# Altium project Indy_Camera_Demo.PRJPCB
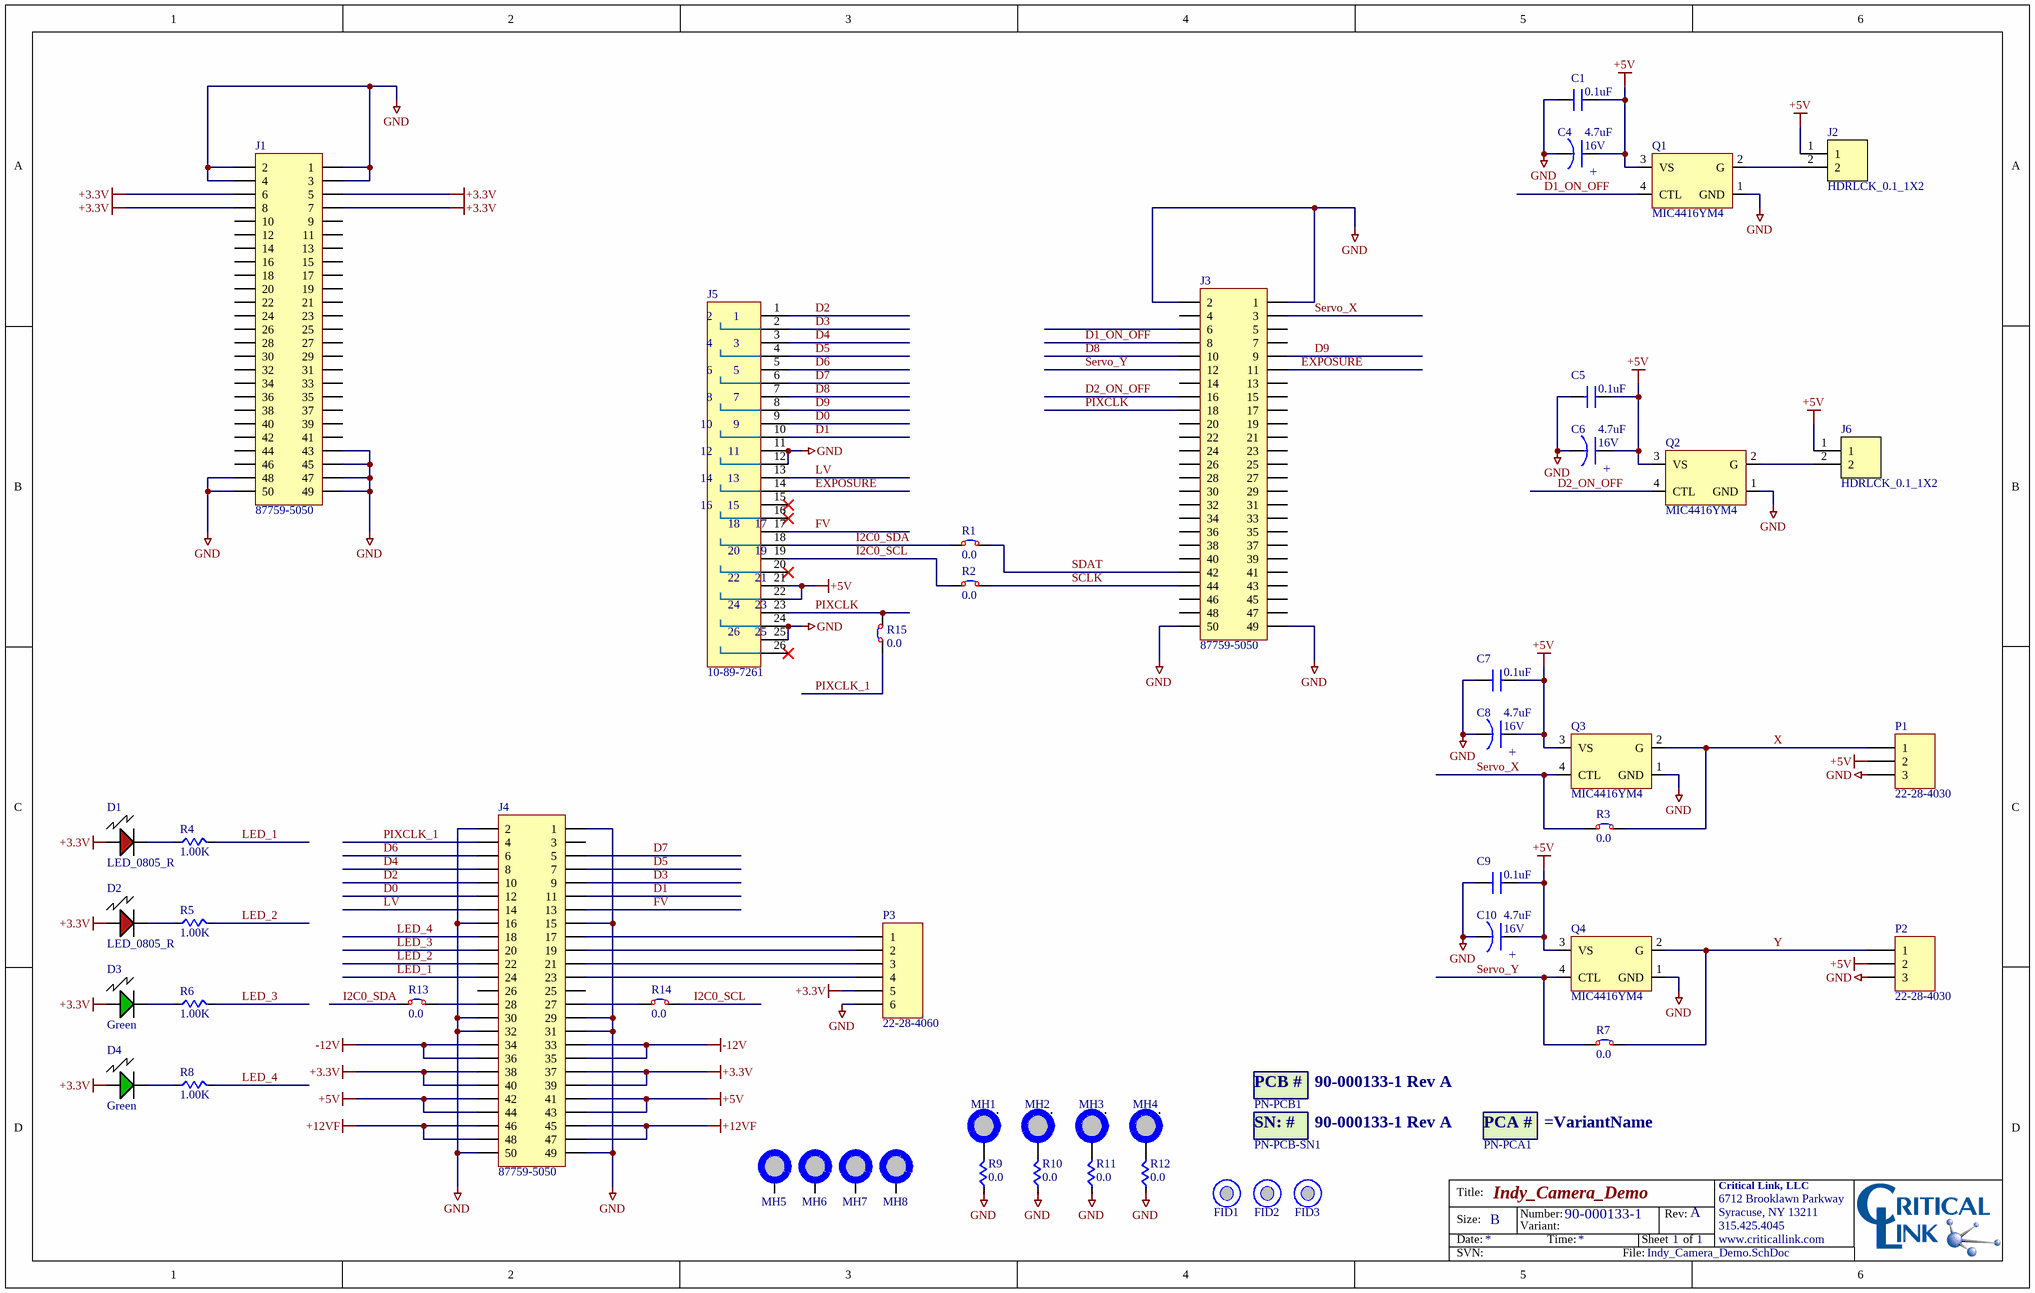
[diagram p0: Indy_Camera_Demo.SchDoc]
1 sheet, 54 parts. Net scope: global (net labels, ports and power ports of the same name join across sheets).
Board file: Indy_Camera_Demo.PcbDoc

## Sheet Indy_Camera_Demo.SchDoc: Indy_Camera_Demo
size B; Organization: Critical Link, LLC; Address1: 6712 Brooklawn Parkway; Address2: Syracuse, NY 13211; Address3: 315.425.4045; Address4: www.criticallink.com; DocumentNumber: 90-000133-1; Revision: A; SheetNumber: 1; SheetTotal: 1; CompanyName: Critical Link, LLC; PageSetup: Record=PageOptions|CenterHorizontal=True|CenterVertical=True|PrintScale=0.70|XCorrection=1.00|YCorrection=1.00|PrintKind=0|BorderSize=5000000|LeftOffset=0|BottomOffset=0|Orientation=2|PaperLength=1000|PaperWidth=1000|Scale=100|PaperSource=7|PrintQuality=-4|MediaType=1|DitherType=10|PaperKind=Letter|PrintScaleMode=1

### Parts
C1  0.1uF  [0603]
C4  4.7uF  Voltage: 16V  [SMD_TAN_A]
C5  0.1uF  [0603]
C6  4.7uF  Voltage: 16V  [SMD_TAN_A]
C7  0.1uF  [0603]
C8  4.7uF  Voltage: 16V  [SMD_TAN_A]
C9  0.1uF  [0603]
C10  4.7uF  Voltage: 16V  [SMD_TAN_A]
D1  LED_0805_R  [LED805]
D2  LED_0805_R  [LED805]
D3  Green  [LED805]
D4  Green  [LED805]
FID1  FIDUCIAL  [FIDUCIAL]  (value not drawn)  (no BOM)
FID2  FIDUCIAL  [FIDUCIAL]  (value not drawn)  (no BOM)
FID3  FIDUCIAL  [FIDUCIAL]  (value not drawn)  (no BOM)
J1  87759-5050  [87759-5050]
J2  HDRLCK_0.1_1X2  [22-23-2021]
J3  87759-5050  [87759-5050]
J4  87759-5050  [87759-5050]
J5  10-89-7261  [HDR_M_100_2x13x240_THR_V_G]
J6  HDRLCK_0.1_1X2  [22-23-2021]
MH1  MH_5-32x  [MH_5-32x]  (value not drawn)  (no BOM)
MH2  MH_5-32x  [MH_5-32x]  (value not drawn)  (no BOM)
MH3  MH_5-32x  [MH_5-32x]  (value not drawn)  (no BOM)
MH4  MH_5-32x  [MH_5-32x]  (value not drawn)  (no BOM)
MH5  MH  [MH125]  (value not drawn)  (no BOM)
MH6  MH  [MH125]  (value not drawn)  (no BOM)
MH7  MH  [MH125]  (value not drawn)  (no BOM)
MH8  MH  [MH125]  (value not drawn)  (no BOM)
P1  22-28-4030  [HDR_M_100_1x3x230_THR]
P2  22-28-4030  [HDR_M_100_1x3x230_THR]
P3  22-28-4060  [HDR1X6]
PN-PCA1  PN-PCA  [PN-PCA]  (value not drawn)  (no BOM)
PN-PCB1  90-000133-1 Rev A  [PN-PCB]  (mechanical)
PN-PCB-SN1  90-000133-1 Rev A  [PN-PCB]  (no BOM)
Q1  MIC4416YM4  [SM/SOT143_1234]
Q2  MIC4416YM4  [SM/SOT143_1234]
Q3  MIC4416YM4  [SM/SOT143_1234]
Q4  MIC4416YM4  [SM/SOT143_1234]
R1  0.0  [0603]
R2  0.0  [0603]
R3  0.0  [0805]
R4  1.00K  [0603]
R5  1.00K  [0603]
R6  1.00K  [0603]
R7  0.0  [0805]
R8  1.00K  [0603]
R9  0.0  [1206]
R10  0.0  [1206]
R11  0.0  [1206]
R12  0.0  [1206]
R13  0.0  [0603]
R14  0.0  [0603]
R15  0.0  [0603]

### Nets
+3.3V: D1.1(A) D2.1(A) D3.1(A) D4.1(A) J1.5 J1.6 J1.7 J1.8 J4.37 J4.38 J4.39 J4.40 P3.5
+5V: C1.1 C4.1 C5.1 C6.1 C7.1 C8.1 C9.1 C10.1 J2.1 J4.41 J4.42 J4.43 J4.44 J5.21(P21) J5.22(P22) J6.1 P1.2 P2.2 Q1.3(VS) Q2.3(VS) Q3.3(VS) Q4.3(VS)
+12VF: J4.45 J4.46 J4.47 J4.48
-12V: J4.33 J4.34 J4.35 J4.36
GND: C1.2 C4.2 C5.2 C6.2 C7.2 C8.2 C9.2 C10.2 J1.1 J1.2 J1.3 J1.4 J1.43 J1.45 J1.47 J1.48 J1.49 J1.50 J3.1 J3.2 J3.49 J3.50 J4.1 J4.2 J4.15 J4.16 J4.29 J4.30 J4.31 J4.32 J4.49 J4.50 J5.11(P11) J5.12(P12) J5.24(P24) J5.25(P25) P1.3 P2.3 P3.6 Q1.1(GND) Q2.1(GND) Q3.1(GND) Q4.1(GND) R9.2 R10.2 R11.2 R12.2
D0: J4.12 J5.9(P9)
D1: J4.11 J5.10(P10)
D1_ON_OFF: J3.8 Q1.4(CTL)
D2: J4.10 J5.1(P1)
D2_ON_OFF: J3.16 Q2.4(CTL)
D3: J4.9 J5.2(P2)
D4: J4.8 J5.3(P3)
D5: J4.7 J5.4(P4)
D6: J4.6 J5.5(P5)
D7: J4.5 J5.6(P6)
D8: J3.10 J5.7(P7)
D9: J3.9 J5.8(P8)
EXPOSURE: J3.11 J5.14(P14)
FV: J4.13 J5.17(P17)
I2C0_SCL: J5.19(P19) R2.1(TOP) R14.2(BOT)
I2C0_SDA: J5.18(P18) R1.1(TOP) R13.1(TOP)
LED_1: J4.24 R4.1
LED_2: J4.22 R5.1
LED_3: J4.20 R6.1
LED_4: J4.18 R8.1
LV: J4.14 J5.13(P13)
PIXCLK: J3.18 J5.23(P23) R15.2(BOT)
PIXCLK_1: J4.4 R15.1(TOP)
SCLK: J3.44 R2.2(BOT)
SDAT: J3.42 R1.2(BOT)
Servo_X: J3.3 Q3.4(CTL) R3.1(TOP)
Servo_Y: J3.12 Q4.4(CTL) R7.1(TOP)
X: P1.1 Q3.2(G) R3.2(BOT)
Y: P2.1 Q4.2(G) R7.2(BOT)
NetD1_2: D1.2(C) R4.2
NetD2_2: D2.2(C) R5.2
NetD3_2: D3.2(C) R6.2
NetD4_2: D4.2(C) R8.2
NetJ2_2: J2.2 Q1.2(G)
NetJ4_17: J4.17 P3.1
NetJ4_19: J4.19 P3.2
NetJ4_21: J4.21 P3.3
NetJ4_23: J4.23 P3.4
NetJ4_27: J4.27 R14.1(TOP)
NetJ4_28: J4.28 R13.2(BOT)
NetJ6_2: J6.2 Q2.2(G)
NetMH1_0: MH1.0 R9.1
NetMH2_0: MH2.0 R10.1
NetMH3_0: MH3.0 R11.1
NetMH4_0: MH4.0 R12.1

Not connected (* = marked no-connect by the designer): J1 9 10 11 12 13 14 15 16 17 18 19 20 21 22 23 24 25 26 27 28 29 30 31 32 33 34 35 36 37 38 39 40 41 42 44 46; J3 4 5 6 7 13 14 15 17 19 20 21 22 23 24 25 26 27 28 29 30 31 32 33 34 35 36 37 38 39 40 41 43 45 46 47 48; J4 3 25 26; J5 15(P15)* 16(P16)* 20(P20)* 26(P26)*; MH1 1; MH2 1; MH3 1; MH4 1; MH5 0; MH6 0; MH7 0; MH8 0

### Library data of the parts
C1 C5 C7 C9 = CAP_X7R_0603_50V: CAP CER .10UF 50V X7R 10% 0603; Part_Type: Ceramic; Type: capacitor; User: Adam; Mfg_PN: 06035C104KAT2A; Dist1: Digi-Key; Dist1_PN: 478-5052-1-ND; Mfg: AVX Corporation; PbFree_Status: Lead free; $/100: 0.048800; $/500: 0.028120; $/1000: 0.019500; ID: 66; Mfg_PID: 5406; QtyAvail: 443230; dist_PID: 1629; dist_pref: 100; $/10: 0.083000; $/ea: 0.000000
C4 C6 C8 C10 = T491A475K016AT: CAPACITOR TANT 4.7UF 16V 10% SMD; Mfg: Kemet; Dist1_PN: 399-3697-1-ND; Dist1: Digi-Key; User: Huy; PbFree_Status: Lead Free; $/100: 0.152000; $/500: 0.120000; $/1000: 0.100000; $/ea: 0.200000; ID: 2503; Mfg_PID: 3119; QtyAvail: 3280; dist_PID: 3127; dist_pref: 100
D1 D2 = LED_0805_R: LED SUPER RED CLEAR 0805 SMD; Mfg: CML Innovative Technologies Inc; Mfg_PN: CMD17-21SRC/TR8; Type: general; $/100: 0.280000; $/ea: 0.390000; Dist1: Digi-Key; Dist1_PN: L62411CT-ND; PbFree_Status: Unknown; QtyAvail: 2177; $/10: 0.336000; Mfg_PID: 1628; pref: 100; ID: 1624
D3 D4 = LED805_G: LED THIN 565NM GRN DIFF 0805 SMD; Mfg: Lumex Opto; Mfg_PN: SML-LXT0805GW-TR; User: MikeP; Dist1: Digi-Key; Dist1_PN: 67-1553-1-ND; Type: general; PbFree_Status: Lead Free; $/10: 0.113000; $/100: 0.090000; $/500: 0.083260; $/ea: 0.140000; ID: 11; Mfg_PID: 1586; QtyAvail: 7092
FID1-FID3 = FIDUCIAL: Fiducial mark
J1 J3 J4 = HDR_M_2mm_2x25x150_SMD_V_G: CONN HEADER 50POS 2MM VERT SMD; Mfg: Molex; User: Oscar; Dist1: Digi-Key; Dist1_PN: WM18672-ND; $/10: 5.686000; $/100: 3.790800; $/500: 3.032660; $/1000: 2.517110; $/ea: 6.440000; ID: 1612; PbFree_Status: Lead Free; QtyAvail: 302
J2 J6 = 22-23-2021: CONN HEADER 2POS .100 VERT TIN; Mfg: Molex; User: MikeP; $/100: 0.198500; $/500: 0.158780; $/1000: 0.131790; $/5000: 0.119090; $/ea: 0.340000; Dist1: Digi-Key; Dist1_PN: WM4200-ND; QtyAvail: 39686; ID: 15; PbFree_Status: Lead Free; $/10: 0.298000
J5 = HDR_M_100_2x13x240_THR_V_G: CONN HDR DUAL 26POS .100 SRT TIN; Mfg: Molex; Dist1_PN: WM26926-ND; Dist1: Digi-Key; User: Huy; $/100: 1.644100; $/500: 1.315240; $/1000: 1.091650; $/5000: 0.986430; $/ea: 2.790000; ID: 4176; Mfg_PID: 4825; PbFree_Status: Lead free; QtyAvail: 0
P1 P2 = HDR_M_100_1x3x230_THR_V: CONN HEADER 3POS .100 VERT TIN; Mfg: Molex; Dist1_PN: WM6403-ND; Dist1: Digi-Key; User: Oscar; $/100: 0.197100; $/500: 0.157660; $/1000: 0.130860; $/5000: 0.118250; $/ea: 0.340000; ID: 3726; Mfg_PID: 4364; PbFree_Status: Lead free; QtyAvail: 0
P3 = HDR_M_100_1x6x230_THR_V: CONN HEADER 6POS .100 VERT TIN; Mfg: Molex; Dist1_PN: WM6406-ND; Dist1: Digi-Key; User: Oscar; $/100: 0.269200; $/500: 0.215340; $/1000: 0.178730; $/5000: 0.161510; $/ea: 0.460000; ID: 4170; Mfg_PID: 4819; PbFree_Status: Lead free; QtyAvail: 0
PN-PCA1 = PN-PCA: PCA Part number; Mfg: Critical Link, LLC; User: MikeP
PN-PCB1 = PN-PCB: PCB Part Number; Mfg: Critical Link, LLC; User: MikeP
PN-PCB-SN1 = PN-PCB-SN: PCB Serial Number and Part Number
Q1-Q4 = MIC4416YM4: IC DRIVER MOSF LOW SIDE SOT143-4; Mfg: Micrel Inc; Dist1_PN: 576-1187-1-ND; Dist1: Digi-Key; User: Huy; Type: general; PbFree_Status: Lead Free; $/10: 1.290000; $/100: 0.860000; $/500: 0.602000; ID: 2510; Mfg_PID: 3126; QtyAvail: 3120; dist_PID: 3134; dist_pref: 100
R1 R2 R13-R15 = ZERO_0603: RES 0.0 OHM 1/10W 5% 0603 SMD; User: MikeP; $/10: 0.069000; $/100: 0.037200; $/500: 0.021400; $/1000: 0.014620; Dist1: Digi-Key; Dist1_PN: RHM0.0GCT-ND; ID: 1628; Mfg: Rohm; Mfg_PID: 1632; Mfg_PN: MCR03EZPJ000; PbFree_Status: Lead Free; QtyAvail: 13750
R3 R7 = ZERO_0805: RES 0.0 OHM 1/8W 5% 0805 SMD; User: MikeP; Power: 1/10W; $/10: 0.076000; $/100: 0.040800; $/500: 0.023400; $/1000: 0.015950; $/ea: 0.000000; Dist1: Digi-Key; Dist1_PN: RHM0.0ACT-ND; ID: 23; Mfg: Rohm; Mfg_PN: MCR10EZHJ000; PbFree_Status: Lead Free; QtyAvail: 7140
R4-R6 R8 = RES_0603: RES 1.00K OHM 1/10W 1% 0603 SMD; Part_Type: Chip Resistor; User: Adam; $/10: 0.076000; $/100: 0.040800; $/500: 0.023400; $/1000: 0.015950; $/ea: 0.000000; Dist1: Digi-Key; Dist1_PN: RHM1.00KHCT-ND; ID: 294; Mfg: Rohm; Mfg_PN: MCR03EZPFX1001; PbFree_Status: Lead Free; QtyAvail: 16180
R9-R12 = RES_1206: RES  0.0 OHM 1/4W 5% 1206 SMD; Part_Type: Chip Resistor; Tolerance: 1%; $/10: 0.078000; $/100: 0.042200; $/500: 0.024250; $/1000: 0.016530; $/ea: 0.000000; Dist1: Digi-Key; Dist1_PN: 311-0.0ERCT-ND; Mfg: Yageo Corporation; Mfg_PN: RC1206JR-070RL; PbFree_Status: Lead Free; QtyAvail: 22900; ID: 2324; Mfg_PID: 2909

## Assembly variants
80-000322RI-1_RevA: not fitted R1 R2 R3 R7 R15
